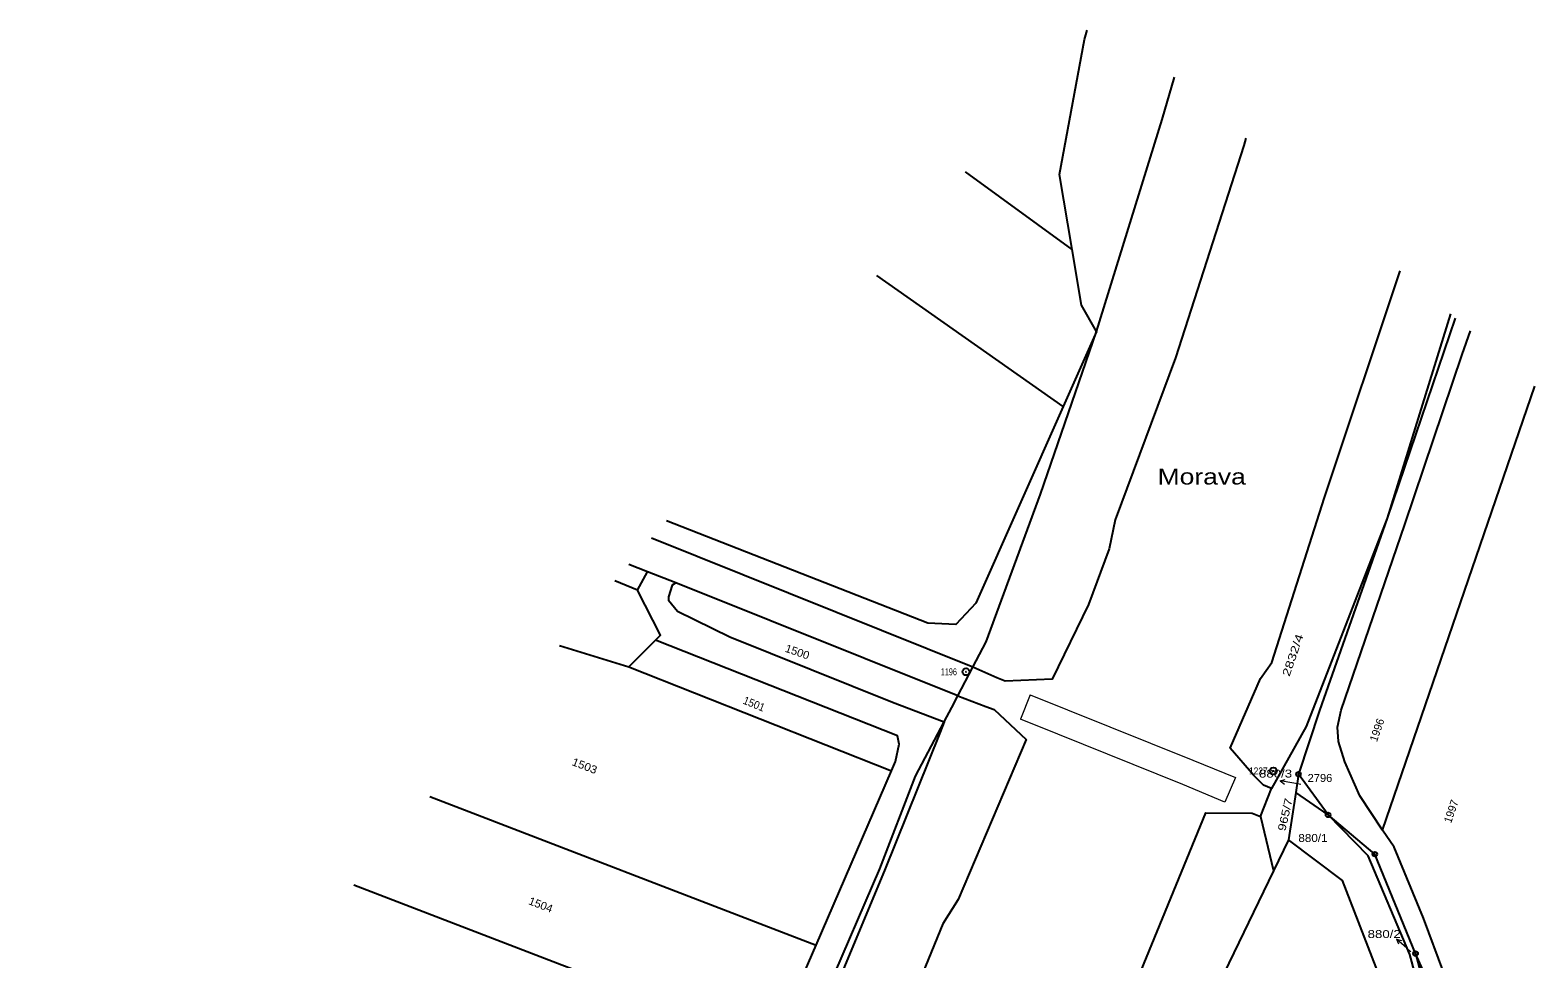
# Model space of a CAD drawing. Extents: x -546984 to -546090, y -1194931 to -1194069.
# Drawn here: x -546588.4 to -546264.7, y -1194268.1 to -1194068.7 of the extents above; entities that cross this region are included whole.
import ezdxf
from ezdxf.enums import TextEntityAlignment as Align

# ---------------------------------------------------------------- set-up
doc = ezdxf.new("R2010")
doc.units = 0
doc.header["$LTSCALE"] = 0.68
for name, color, linetype, lineweight in [('1', 7, 'Continuous', 25), ('4', 7, 'Continuous', 13), ('7', 7, 'Continuous', 13), ('8', 7, 'Continuous', 25)]:
    doc.layers.add(name, color=color, linetype=linetype, lineweight=lineweight)
doc.layers.add('2', color=7, linetype='Continuous')

msp = doc.modelspace()

# ---------------------------------------------------------------- linework, layer by layer
at = {"layer": '1'}
for p, q in [((-546366.63, -1194149.5), (-546406.652, -1194121.37)), ((-546283.467, -1194129.605), (-546297.04, -1194173.48)), ((-546282.428, -1194130.496), (-546297.04, -1194173.48)), ((-546359.49, -1194133.42), (-546366.63, -1194149.5)), ((-546298.03, -1194240.43), (-546265.384, -1194145.118)), ((-546386.02, -1194205.45), (-546454.994, -1194177.721)), ((-546449.81, -1194187.37), (-546455.85, -1194185.01)), ((-546458.04, -1194188.88), (-546462.898, -1194186.935)), ((-546389.24, -1194211.62), (-546449.81, -1194187.37)), ((-546474.786, -1194200.793), (-546459.86, -1194205.4)), ((-546389.24, -1194211.62), (-546386.02, -1194205.45)), ((-546316.1, -1194228.43), (-546316.69, -1194232.35)), ((-546316.69, -1194232.35), (-546318.22, -1194242.52)), ((-546324.23, -1194237.51), (-546321.44, -1194249.16)), ((-546318.22, -1194242.52), (-546321.44, -1194249.16)), ((-546321.44, -1194249.16), (-546333.19, -1194273.39))]:
    msp.add_line(p, q, dxfattribs=at)
for points in [[(-546364.69, -1194115.76), (-546367.39, -1194099.66), (-546362.06, -1194070.72), (-546361.471, -1194068.703)], [(-546359.49, -1194133.42), (-546345.37, -1194087.87), (-546342.69, -1194078.799)], [(-546327.431, -1194091.89), (-546327.86, -1194093.44), (-546342.49, -1194139.05), (-546355.46, -1194173.85), (-546356.73, -1194180.07), (-546361.2, -1194191.98), (-546369, -1194208.01), (-546379.07, -1194208.43), (-546380.85, -1194207.74), (-546386.02, -1194205.45)], [(-546359.49, -1194133.42), (-546362.68, -1194127.72), (-546364.69, -1194115.76), (-546387.575, -1194099.133)], [(-546321.88, -1194231.5), (-546323.62, -1194230.74), (-546325.69, -1194228.72), (-546330.76, -1194222.84), (-546324.29, -1194207.87), (-546321.84, -1194204.42), (-546310.55, -1194169.01), (-546294.278, -1194120.33)], [(-546386.02, -1194205.45), (-546383.17, -1194199.98), (-546371.46, -1194168.28), (-546359.49, -1194133.42)], [(-546298.03, -1194240.43), (-546302.96, -1194233.06), (-546306.14, -1194225.76), (-546307.52, -1194221.37), (-546307.69, -1194218.3), (-546306.97, -1194214.64), (-546293.26, -1194174.79), (-546280.94, -1194138.32), (-546279.188, -1194133.275)], [(-546366.63, -1194149.5), (-546385.38, -1194191.7), (-546389.64, -1194196.31), (-546395.68, -1194196), (-546451.799, -1194173.997)], [(-546297.04, -1194173.48), (-546314.46, -1194218.15), (-546321.88, -1194231.5)], [(-546297.04, -1194173.48), (-546311.59, -1194214.77), (-546316.1, -1194228.43)], [(-546458.04, -1194188.88), (-546455.85, -1194185.01), (-546459.861, -1194183.395)], [(-546454.12, -1194199.66), (-546453.05, -1194198.6), (-546458.04, -1194188.88)], [(-546449.81, -1194187.37), (-546450.58, -1194187.83), (-546451.34, -1194190.33), (-546451.38, -1194191.09), (-546449.41, -1194193.4), (-546438.19, -1194198.94), (-546403.26, -1194212.96), (-546392.14, -1194217.18)], [(-546454.12, -1194199.66), (-546459.86, -1194205.4), (-546403.51, -1194227.7)], [(-546403.51, -1194227.7), (-546402.63, -1194225.66), (-546401.86, -1194221.95), (-546402.19, -1194220.21), (-546454.12, -1194199.66)], [(-546389.24, -1194211.62), (-546383.21, -1194213.85), (-546381.43, -1194214.52), (-546374.55, -1194220.96), (-546389.16, -1194255.29), (-546392.45, -1194260.52), (-546401.16, -1194281.84), (-546427.1, -1194334), (-546466.91, -1194406.62), (-546525.73, -1194500.91), (-546575.37, -1194569.17), (-546611.42, -1194614.13), (-546654.08, -1194661.28), (-546675.45, -1194680.69), (-546700.89, -1194697.8)], [(-546392.14, -1194217.18), (-546390.55, -1194214.13), (-546389.24, -1194211.62)], [(-546480.28, -1194398.62), (-546454.62, -1194351.38), (-546441.74, -1194326.26), (-546429.78, -1194301.03), (-546417.24, -1194274.74), (-546406, -1194248.75), (-546398.33, -1194228.83), (-546392.14, -1194217.18)], [(-546392.14, -1194217.18), (-546393.03, -1194219.38), (-546404.99, -1194249.12), (-546415.92, -1194275.33), (-546428.91, -1194301.5), (-546441.35, -1194326.56), (-546453.74, -1194351.98), (-546480.28, -1194398.62)], [(-546502.609, -1194233.225), (-546419.67, -1194265.11), (-546403.51, -1194227.7)], [(-546290.97, -1194266.91), (-546299.71, -1194245.58), (-546309.75, -1194237.15), (-546316.1, -1194228.43)], [(-546653.83, -1194720.11), (-546626.66, -1194696.55), (-546572.27, -1194633.02), (-546541.58, -1194595.62), (-546489.43, -1194522.46), (-546452.3, -1194465.52), (-546414.56, -1194402.38), (-546384.23, -1194347.08), (-546351.57, -1194280.62), (-546352.84, -1194277.72), (-546335.99, -1194236.72), (-546326.04, -1194236.79), (-546324.23, -1194237.51), (-546321.88, -1194231.5)], [(-546290.97, -1194266.91), (-546283.11, -1194296.25), (-546283.98, -1194297.43), (-546292.16, -1194267.14), (-546301.17, -1194245.95), (-546309.75, -1194237.15), (-546316.69, -1194232.35)], [(-546223.97, -1194273.81), (-546237.14, -1194276.93), (-546278.51, -1194283.23), (-546280.55, -1194282.82), (-546289.26, -1194259.3), (-546295.56, -1194244.05), (-546298.03, -1194240.43)], [(-546264.98, -1194358.54), (-546288.15, -1194295.14), (-546291.74, -1194295.93), (-546299.4, -1194269.93), (-546306.67, -1194251.25), (-546318.22, -1194242.52)], [(-546518.881, -1194252.193), (-546429.01, -1194286.74), (-546419.67, -1194265.11)], [(-546239.33, -1194397.92), (-546258.87, -1194346.57), (-546279.19, -1194293.17), (-546290.97, -1194266.91)]]:
    msp.add_lwpolyline(points, dxfattribs=at)
at = {"layer": '4'}
for p, q in [((-546373.69, -1194211.41), (-546375.76, -1194216.57)), ((-546329.62, -1194229.14), (-546331.91, -1194234.4))]:
    msp.add_line(p, q, dxfattribs=at)
for points in [[(-546373.69, -1194211.41), (-546365.66, -1194214.63), (-546338.81, -1194225.43), (-546329.62, -1194229.14)], [(-546331.91, -1194234.4), (-546340.96, -1194230.62), (-546367.8, -1194219.83), (-546375.76, -1194216.57)]]:
    msp.add_lwpolyline(points, dxfattribs=at)
at = {"layer": '7'}
for p, q in [((-546320.025, -1194229.855), (-546319.126, -1194230.522)), ((-546295.075, -1194263.801), (-546294.648, -1194264.836))]:
    msp.add_line(p, q, dxfattribs=at)
for points in [[(-546315.59, -1194230.626), (-546317.07, -1194230.376), (-546320.025, -1194229.855), (-546318.952, -1194229.536)], [(-546291.95, -1194266.53), (-546292.81, -1194265.77), (-546295.075, -1194263.801), (-546293.991, -1194264.08)]]:
    msp.add_lwpolyline(points, dxfattribs=at)
at = {"layer": '8'}
for centre, radius in [((-546387.47, -1194206.4398), 0.75), ((-546387.47, -1194206.4398), 0.03), ((-546321.5, -1194227.7198), 0.75), ((-546321.5, -1194227.7198), 0.03), ((-546316.1, -1194228.4299), 0.5), ((-546316.1, -1194228.4299), 0.0303), ((-546309.75, -1194237.1499), 0.5), ((-546309.75, -1194237.1499), 0.0303), ((-546299.71, -1194245.5799), 0.5), ((-546299.71, -1194245.5799), 0.0303), ((-546290.97, -1194266.9099), 0.5), ((-546290.97, -1194266.9099), 0.0303)]:
    msp.add_circle(centre, radius, dxfattribs=at)

# ---------------------------------------------------------------- texts
at = {"layer": '2'}
for s, rotation, width, p in [('2832/4', 71.129, 1.35, (-546318.04, -1194207.579)), ('1500', 341, 1.05, (-546426.476, -1194202.093)), ('1501', 338, 0.95, (-546435.528, -1194213.218)), ('1503', 339, 1.1, (-546472.264, -1194226.423)), ('965/7', 77, 1.25, (-546318.94, -1194240.748)), ('1504', 339, 1.05, (-546481.554, -1194256.283))]:
    msp.add_text(s, height=1.7, rotation=rotation, dxfattribs=dict(at, width=width)).set_placement(p)
for s, p in [('1996', (-546299.268, -1194221.6)), ('1997', (-546283.345, -1194239.058))]:
    msp.add_text(s, height=1.7, rotation=71, dxfattribs=at).set_placement(p)
at = {"layer": '2', "width": 1.25}
for s, p in [('880/3', (-546317.472, -1194229.133)), ('880/2', (-546294.146, -1194263.578))]:
    msp.add_text(s, height=1.7, dxfattribs=at).set_placement(p, align=Align.RIGHT)
at = {"layer": '2', "width": 1.05}
msp.add_text('2796', height=1.7, dxfattribs=at).set_placement((-546314.145, -1194230.075))
at = {"layer": '2', "width": 1.1}
msp.add_text('880/1', height=1.7, dxfattribs=at).set_placement((-546312.999, -1194242.96), align=Align.CENTER)
at = {"layer": '7', "width": 1.25}
msp.add_text('Morava', height=3.4, dxfattribs=at).set_placement((-546346.352, -1194166.235))
at = {"layer": '8'}
for s, width, p in [('1196', 0.75, (-546389.435, -1194207.19)), ('1227', 0.9, (-546322.71, -1194228.47))]:
    msp.add_text(s, height=1.5, dxfattribs=dict(at, width=width)).set_placement(p, align=Align.RIGHT)

doc.saveas('drawing.dxf')
